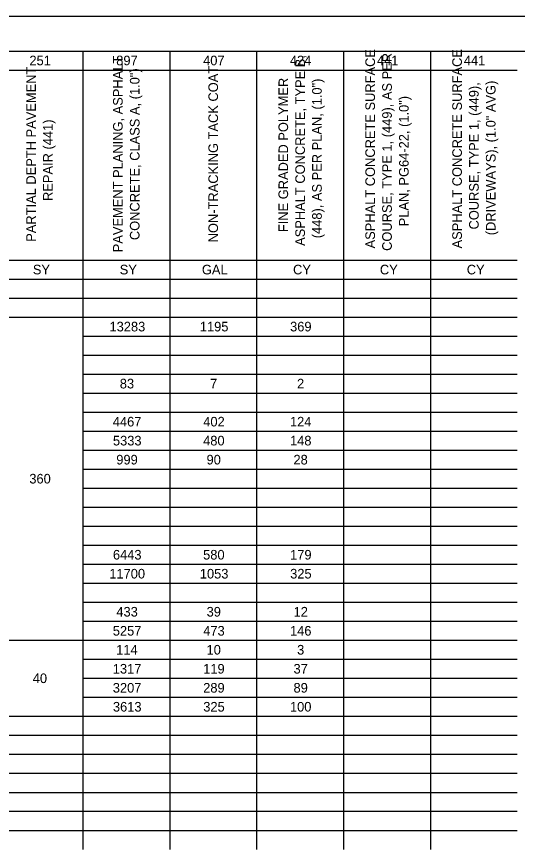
# Model space of a CAD drawing. Extents: x 0 to 34, y 0 to 22.
# Drawn here: x 19.65 to 26.94, y 9.88 to 22 of the extents above; entities that cross this region are included whole.
import ezdxf

# ---------------------------------------------------------------- set-up
doc = ezdxf.new("R2010")
doc.units = 0
for name, color, linetype in [('SH_Border', 7, 'Continuous'), ('SH_Cut_Line', 7, 'Continuous'), ('SH_Text', 7, 'Continuous')]:
    doc.layers.add(name, color=color, linetype=linetype)

msp = doc.modelspace()

# ---------------------------------------------------------------- linework, layer by layer
at = {"layer": 'SH_Border'}
msp.add_lwpolyline([(1.5, 21.5), (33.5, 21.5), (33.5, 0.5), (1.5, 0.5)], close=True, dxfattribs=at)
at = {"layer": 'SH_Cut_Line'}
msp.add_lwpolyline([(0, 0), (34, 0), (34, 22), (0, 22)], close=True, dxfattribs=at)
at = {"layer": 'SH_Text'}
for p, q in [((15.556, 21.5), (23.145, 21.5)), ((20.616, 21.5), (20.616, 21.223)), ((21.88, 21.5), (21.88, 21.223)), ((23.145, 21.5), (24.41, 21.5)), ((23.145, 21.5), (23.145, 21.223)), ((24.41, 21.5), (25.675, 21.5)), ((24.41, 21.5), (24.41, 21.223)), ((25.675, 21.5), (26.94, 21.5)), ((25.675, 21.5), (25.675, 21.223)), ((18.086, 21.223), (23.145, 21.223)), ((20.616, 21.223), (20.616, 20.947)), ((21.88, 21.223), (21.88, 20.947)), ((23.145, 21.223), (24.41, 21.223)), ((23.145, 21.223), (23.145, 20.947)), ((24.41, 21.223), (25.675, 21.223)), ((24.41, 21.223), (24.41, 20.947)), ((25.675, 21.223), (26.94, 21.223)), ((25.675, 21.223), (25.675, 20.947)), ((20.616, 20.947), (20.616, 20.67)), ((21.88, 20.947), (21.88, 20.67)), ((23.145, 20.947), (23.145, 20.67)), ((24.41, 20.947), (24.41, 20.67)), ((25.675, 20.947), (25.675, 20.67)), ((20.616, 20.67), (20.616, 20.393)), ((21.88, 20.67), (21.88, 20.393)), ((23.145, 20.67), (23.145, 20.393)), ((24.41, 20.67), (24.41, 20.393)), ((25.675, 20.67), (25.675, 20.393)), ((20.616, 20.393), (20.616, 20.116)), ((21.88, 20.393), (21.88, 20.116)), ((23.145, 20.393), (23.145, 20.116)), ((24.41, 20.393), (24.41, 20.116)), ((25.675, 20.393), (25.675, 20.116)), ((20.616, 20.116), (20.616, 19.84)), ((21.88, 20.116), (21.88, 19.84)), ((23.145, 20.116), (23.145, 19.84)), ((24.41, 20.116), (24.41, 19.84)), ((25.675, 20.116), (25.675, 19.84)), ((20.616, 19.84), (20.616, 19.563)), ((21.88, 19.84), (21.88, 19.563)), ((23.145, 19.84), (23.145, 19.563)), ((24.41, 19.84), (24.41, 19.563)), ((25.675, 19.84), (25.675, 19.563)), ((20.616, 19.563), (20.616, 19.01)), ((21.88, 19.563), (21.88, 19.01)), ((23.145, 19.563), (23.145, 19.01)), ((24.41, 19.563), (24.41, 19.01)), ((25.675, 19.563), (25.675, 19.01)), ((20.616, 19.01), (20.616, 18.18)), ((21.88, 19.01), (21.88, 18.18)), ((23.145, 19.01), (23.145, 18.18)), ((24.41, 19.01), (24.41, 18.18)), ((25.675, 19.01), (25.675, 18.18)), ((15.556, 18.456), (23.145, 18.456)), ((23.145, 18.456), (24.41, 18.456)), ((24.41, 18.456), (25.675, 18.456)), ((25.675, 18.456), (26.94, 18.456)), ((15.556, 18.18), (23.145, 18.18)), ((20.616, 18.18), (20.616, 17.349)), ((21.88, 18.18), (21.88, 17.349)), ((23.145, 18.18), (24.41, 18.18)), ((23.145, 18.18), (23.145, 17.349)), ((24.41, 18.18), (25.675, 18.18)), ((24.41, 18.18), (24.41, 17.349)), ((25.675, 18.18), (26.94, 18.18)), ((25.675, 18.18), (25.675, 17.349)), ((15.556, 17.903), (23.145, 17.903)), ((23.145, 17.903), (24.41, 17.903)), ((24.41, 17.903), (25.675, 17.903)), ((25.675, 17.903), (26.94, 17.903)), ((15.556, 17.626), (23.145, 17.626)), ((23.145, 17.626), (24.41, 17.626)), ((24.41, 17.626), (25.675, 17.626)), ((25.675, 17.626), (26.94, 17.626)), ((20.616, 17.349), (23.145, 17.349)), ((20.616, 17.349), (20.616, 17.073)), ((21.88, 17.349), (21.88, 17.073)), ((23.145, 17.349), (24.41, 17.349)), ((23.145, 17.349), (23.145, 17.073)), ((24.41, 17.349), (25.675, 17.349)), ((24.41, 17.349), (24.41, 17.073)), ((25.675, 17.349), (26.94, 17.349)), ((25.675, 17.349), (25.675, 17.073)), ((20.616, 17.073), (23.145, 17.073)), ((20.616, 17.073), (20.616, 15.966)), ((21.88, 17.073), (21.88, 15.966)), ((23.145, 17.073), (24.41, 17.073)), ((23.145, 17.073), (23.145, 15.966)), ((24.41, 17.073), (25.675, 17.073)), ((24.41, 17.073), (24.41, 15.966)), ((25.675, 17.073), (26.94, 17.073)), ((25.675, 17.073), (25.675, 15.966)), ((20.616, 16.796), (23.145, 16.796)), ((23.145, 16.796), (24.41, 16.796)), ((24.41, 16.796), (25.675, 16.796)), ((25.675, 16.796), (26.94, 16.796)), ((20.616, 16.519), (23.145, 16.519)), ((23.145, 16.519), (24.41, 16.519)), ((24.41, 16.519), (25.675, 16.519)), ((25.675, 16.519), (26.94, 16.519)), ((20.616, 16.243), (23.145, 16.243)), ((23.145, 16.243), (24.41, 16.243)), ((24.41, 16.243), (25.675, 16.243)), ((25.675, 16.243), (26.94, 16.243)), ((20.616, 15.966), (23.145, 15.966)), ((20.616, 15.966), (20.616, 15.689)), ((21.88, 15.966), (21.88, 15.689)), ((23.145, 15.966), (24.41, 15.966)), ((23.145, 15.966), (23.145, 15.689)), ((24.41, 15.966), (25.675, 15.966)), ((24.41, 15.966), (24.41, 15.689)), ((25.675, 15.966), (26.94, 15.966)), ((25.675, 15.966), (25.675, 15.689)), ((20.616, 15.689), (23.145, 15.689)), ((20.616, 15.689), (20.616, 15.136)), ((21.88, 15.689), (21.88, 15.136)), ((23.145, 15.689), (24.41, 15.689)), ((23.145, 15.689), (23.145, 15.136)), ((24.41, 15.689), (25.675, 15.689)), ((24.41, 15.689), (24.41, 15.136)), ((25.675, 15.689), (26.94, 15.689)), ((25.675, 15.689), (25.675, 15.136)), ((20.616, 15.412), (23.145, 15.412)), ((23.145, 15.412), (24.41, 15.412)), ((24.41, 15.412), (25.675, 15.412)), ((25.675, 15.412), (26.94, 15.412)), ((20.616, 15.136), (23.145, 15.136)), ((20.616, 15.136), (20.616, 14.582)), ((21.88, 15.136), (21.88, 14.582)), ((23.145, 15.136), (24.41, 15.136)), ((23.145, 15.136), (23.145, 14.582)), ((24.41, 15.136), (25.675, 15.136)), ((24.41, 15.136), (24.41, 14.582)), ((25.675, 15.136), (26.94, 15.136)), ((25.675, 15.136), (25.675, 14.582)), ((20.616, 14.859), (23.145, 14.859)), ((23.145, 14.859), (24.41, 14.859)), ((24.41, 14.859), (25.675, 14.859)), ((25.675, 14.859), (26.94, 14.859)), ((20.616, 14.582), (23.145, 14.582)), ((20.616, 14.582), (20.616, 14.306)), ((21.88, 14.582), (21.88, 14.306)), ((23.145, 14.582), (24.41, 14.582)), ((23.145, 14.582), (23.145, 14.306)), ((24.41, 14.582), (25.675, 14.582)), ((24.41, 14.582), (24.41, 14.306)), ((25.675, 14.582), (26.94, 14.582)), ((25.675, 14.582), (25.675, 14.306)), ((20.616, 14.306), (23.145, 14.306)), ((20.616, 14.306), (20.616, 13.752)), ((21.88, 14.306), (21.88, 13.752)), ((23.145, 14.306), (24.41, 14.306)), ((23.145, 14.306), (23.145, 13.752)), ((24.41, 14.306), (25.675, 14.306)), ((24.41, 14.306), (24.41, 13.752)), ((25.675, 14.306), (26.94, 14.306)), ((25.675, 14.306), (25.675, 13.752)), ((20.616, 14.029), (23.145, 14.029)), ((23.145, 14.029), (24.41, 14.029)), ((24.41, 14.029), (25.675, 14.029)), ((25.675, 14.029), (26.94, 14.029)), ((20.616, 13.752), (23.145, 13.752)), ((20.616, 13.752), (20.616, 13.476)), ((21.88, 13.752), (21.88, 13.476)), ((23.145, 13.752), (24.41, 13.752)), ((23.145, 13.752), (23.145, 13.476)), ((24.41, 13.752), (25.675, 13.752)), ((24.41, 13.752), (24.41, 13.476)), ((25.675, 13.752), (26.94, 13.752)), ((25.675, 13.752), (25.675, 13.476)), ((20.616, 13.476), (23.145, 13.476)), ((20.616, 13.476), (20.616, 12.645)), ((21.88, 13.476), (21.88, 12.645)), ((23.145, 13.476), (24.41, 13.476)), ((23.145, 13.476), (23.145, 12.645)), ((24.41, 13.476), (25.675, 13.476)), ((24.41, 13.476), (24.41, 12.645)), ((25.675, 13.476), (26.94, 13.476)), ((25.675, 13.476), (25.675, 12.645)), ((20.616, 13.199), (23.145, 13.199)), ((23.145, 13.199), (24.41, 13.199)), ((24.41, 13.199), (25.675, 13.199)), ((25.675, 13.199), (26.94, 13.199)), ((15.556, 12.922), (23.145, 12.922)), ((23.145, 12.922), (24.41, 12.922)), ((24.41, 12.922), (25.675, 12.922)), ((25.675, 12.922), (26.94, 12.922)), ((20.616, 12.645), (23.145, 12.645)), ((20.616, 12.645), (20.616, 12.369)), ((21.88, 12.645), (21.88, 12.369)), ((23.145, 12.645), (24.41, 12.645)), ((23.145, 12.645), (23.145, 12.369)), ((24.41, 12.645), (25.675, 12.645)), ((24.41, 12.645), (24.41, 12.369)), ((25.675, 12.645), (26.94, 12.645)), ((25.675, 12.645), (25.675, 12.369)), ((20.616, 12.369), (23.145, 12.369)), ((20.616, 12.369), (20.616, 12.092)), ((21.88, 12.369), (21.88, 12.092)), ((23.145, 12.369), (24.41, 12.369)), ((23.145, 12.369), (23.145, 12.092)), ((24.41, 12.369), (25.675, 12.369)), ((24.41, 12.369), (24.41, 12.092)), ((25.675, 12.369), (26.94, 12.369)), ((25.675, 12.369), (25.675, 12.092)), ((20.616, 12.092), (23.145, 12.092)), ((20.616, 12.092), (20.616, 11.262)), ((21.88, 12.092), (21.88, 11.262)), ((23.145, 12.092), (24.41, 12.092)), ((23.145, 12.092), (23.145, 11.262)), ((24.41, 12.092), (25.675, 12.092)), ((24.41, 12.092), (24.41, 11.262)), ((25.675, 12.092), (26.94, 12.092)), ((25.675, 12.092), (25.675, 11.262)), ((15.556, 11.815), (23.145, 11.815)), ((23.145, 11.815), (24.41, 11.815)), ((24.41, 11.815), (25.675, 11.815)), ((25.675, 11.815), (26.94, 11.815)), ((15.556, 11.539), (23.145, 11.539)), ((23.145, 11.539), (24.41, 11.539)), ((24.41, 11.539), (25.675, 11.539)), ((25.675, 11.539), (26.94, 11.539)), ((15.556, 11.262), (23.145, 11.262)), ((20.616, 11.262), (20.616, 10.708)), ((21.88, 11.262), (21.88, 10.708)), ((23.145, 11.262), (24.41, 11.262)), ((23.145, 11.262), (23.145, 10.708)), ((24.41, 11.262), (25.675, 11.262)), ((24.41, 11.262), (24.41, 10.708)), ((25.675, 11.262), (26.94, 11.262)), ((25.675, 11.262), (25.675, 10.708)), ((15.556, 10.985), (23.145, 10.985)), ((23.145, 10.985), (24.41, 10.985)), ((24.41, 10.985), (25.675, 10.985)), ((25.675, 10.985), (26.94, 10.985)), ((15.556, 10.708), (23.145, 10.708)), ((20.616, 10.708), (20.616, 9.878)), ((21.88, 10.708), (21.88, 9.878)), ((23.145, 10.708), (24.41, 10.708)), ((23.145, 10.708), (23.145, 9.878)), ((24.41, 10.708), (25.675, 10.708)), ((24.41, 10.708), (24.41, 9.878)), ((25.675, 10.708), (26.94, 10.708)), ((25.675, 10.708), (25.675, 9.878)), ((15.556, 10.432), (23.145, 10.432)), ((23.145, 10.432), (24.41, 10.432)), ((24.41, 10.432), (25.675, 10.432)), ((25.675, 10.432), (26.94, 10.432)), ((15.556, 10.155), (23.145, 10.155)), ((23.145, 10.155), (24.41, 10.155)), ((24.41, 10.155), (25.675, 10.155)), ((25.675, 10.155), (26.94, 10.155))]:
    msp.add_line(p, q, dxfattribs=at)

# ---------------------------------------------------------------- texts
for s, p in [('ASPHALT CONCRETE SURFACE ', (24.868, 18.626)), ('COURSE, TYPE 1, (449), AS PER ', (25.113, 18.59)), ('ASPHALT CONCRETE SURFACE ', (26.133, 18.626)), ('PAVEMENT PLANING, ASPHALT ', (21.195, 18.57)), ('ASPHALT CONCRETE, TYPE B, ', (23.848, 18.663)), ('PARTIAL DEPTH PAVEMENT ', (19.931, 18.723)), ('CONCRETE, CLASS A, (1.0")', (21.44, 18.747)), ('NON-TRACKING TACK COAT', (22.583, 18.715)), ('FINE GRADED POLYMER ', (23.603, 18.863)), ('(448), AS PER PLAN, (1.0")', (24.093, 18.774)), ('COURSE, TYPE 1, (449), ', (26.378, 18.902)), ('(DRIVEWAYS), (1.0" AVG)', (26.623, 18.818)), ('PLAN, PG64-22, (1.0")', (25.358, 18.948)), ('REPAIR (441)', (20.176, 19.317))]:
    msp.add_text(s, height=0.14, rotation=90, dxfattribs=at).set_placement(p)
for s, p in [('251', (19.837, 21.292)), ('897', (21.101, 21.292)), ('407', (22.366, 21.292)), ('424', (23.629, 21.292)), ('441', (24.896, 21.292)), ('441', (26.161, 21.292)), ('SY', (19.887, 18.248)), ('SY', (21.152, 18.248)), ('GAL', (22.348, 18.248)), ('CY', (23.675, 18.248)), ('CY', (24.939, 18.248)), ('CY', (26.204, 18.248)), ('13283', (21.003, 17.418)), ('1195', (22.318, 17.418)), ('369', (23.632, 17.418)), ('83', (21.153, 16.588)), ('2', (23.733, 16.588)), ('7', (22.467, 16.588)), ('4467', (21.051, 16.034)), ('402', (22.368, 16.034)), ('124', (23.63, 16.034)), ('5333', (21.053, 15.758)), ('480', (22.366, 15.758)), ('148', (23.631, 15.758)), ('999', (21.102, 15.481)), ('90', (22.416, 15.481)), ('28', (23.681, 15.481)), ('360', (19.836, 15.204)), ('6443', (21.053, 14.097)), ('580', (22.366, 14.097)), ('179', (23.632, 14.097)), ('11700', (21, 13.821)), ('1053', (22.318, 13.821)), ('325', (23.633, 13.821)), ('433', (21.103, 13.267)), ('39', (22.417, 13.267)), ('12', (23.683, 13.267)), ('5257', (21.051, 12.99)), ('473', (22.368, 12.99)), ('146', (23.631, 12.99)), ('114', (21.1, 12.714)), ('10', (22.416, 12.714)), ('3', (23.734, 12.714)), ('1317', (21.051, 12.437)), ('119', (22.367, 12.437)), ('37', (23.682, 12.437)), ('40', (19.886, 12.299)), ('3207', (21.051, 12.16)), ('289', (22.367, 12.16)), ('89', (23.682, 12.16)), ('3613', (21.053, 11.884)), ('325', (22.368, 11.884)), ('100', (23.63, 11.884))]:
    msp.add_text(s, height=0.14, dxfattribs=at).set_placement(p)

doc.saveas('drawing.dxf')
